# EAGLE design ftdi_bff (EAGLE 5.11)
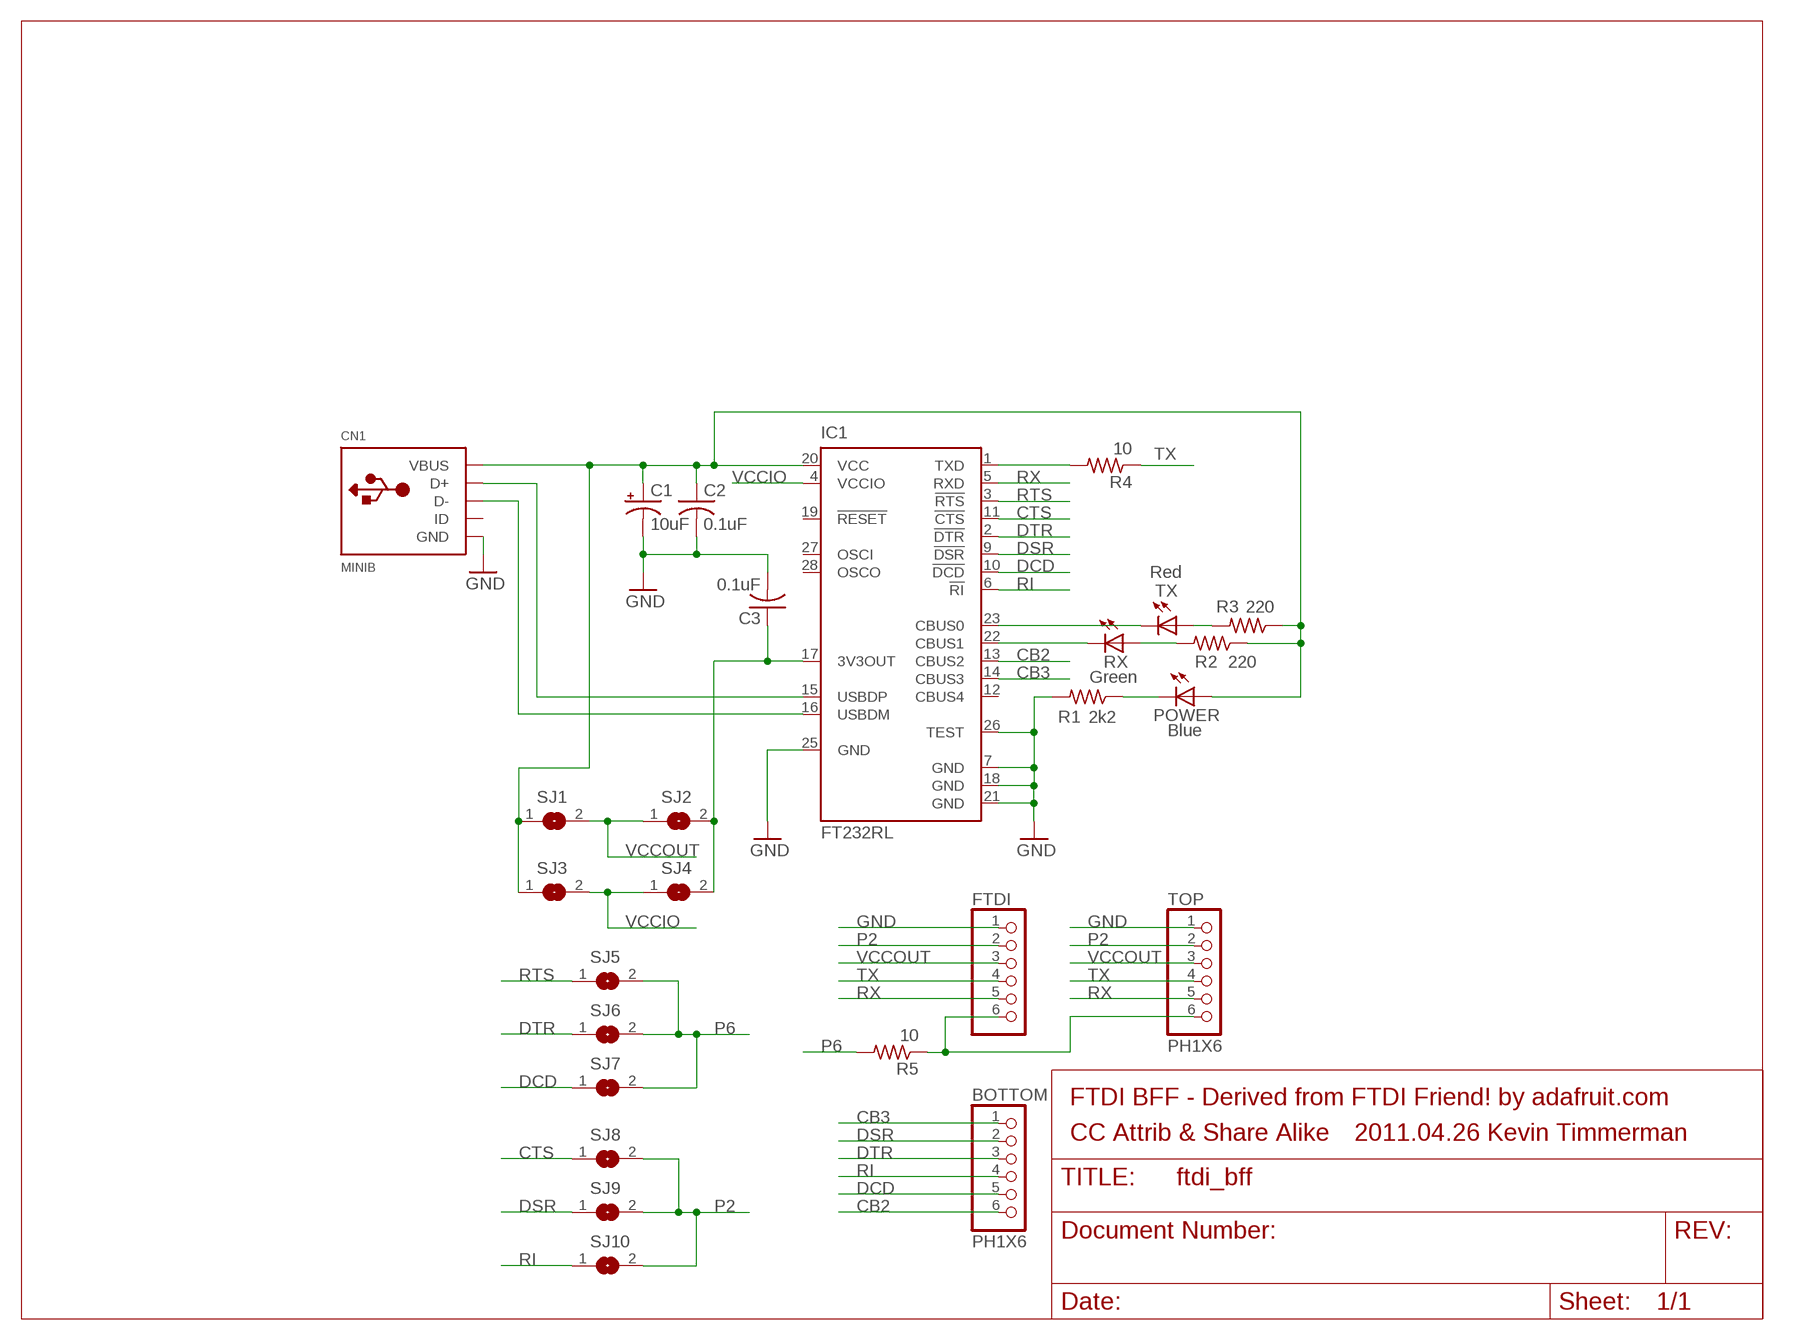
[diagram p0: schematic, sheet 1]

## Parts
BOTTOM  PH1X6  [PH1X6EDGE]
C1  10uF  CPOL-USA/3216-18R  [A/3216-18R]
C2  0.1uF  C-USC0805K  [C0805K]
C3  0.1uF  C-USC0805K  [C0805K]
CN1  MINIB  USBMINIB  [USB-MINIB]
FTDI  PINHD-1X6CB  [1X06-CLEANBIG]
IC1  FT232RL  [SSOP28]
POWER  Blue  LEDCHIP-LED0805  [CHIP-LED0805]
R1  2k2  R-US_R0805  [R0805]
R2  220  R-US_R0805  [R0805]
R3  220  R-US_R0805  [R0805]
R4  10  R-US_R0805  [R0805]
R5  10  R-US_R0805  [R0805]
RX  Green  LEDCHIP-LED0805  [CHIP-LED0805]
SJ1  SJ  [SJ]
SJ2  SJ  [SJ]
SJ3  SJ  [SJ]
SJ4  SJ  [SJ]
SJ5  SJ  [SJ]
SJ6  SJ  [SJ]
SJ7  SJ  [SJ]
SJ8  SJ  [SJ]
SJ9  SJ  [SJ]
SJ10  SJ  [SJ]
TOP  PH1X6  [PH1X6EDGE]
TX  Red  LEDCHIP-LED0805  [CHIP-LED0805]

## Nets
CB2: BOTTOM.6 IC1.13(CBUS2)
CB3: BOTTOM.1 IC1.14(CBUS3)
CTS: IC1.11(!CTS) SJ8.1
DCD: BOTTOM.5 IC1.10(!DCD) SJ7.1
DSR: BOTTOM.2 IC1.9(!DSR) SJ9.1
DTR: BOTTOM.3 IC1.2(!DTR) SJ6.1
GND: C1.- C2.2 C3.2 CN1.GND FTDI.1 IC1.7(GND) IC1.18(GND) IC1.21(GND) IC1.25(GND) IC1.26(TEST) R1.2 TOP.1
N$2: FTDI.6 R5.1 TOP.6
N$3: CN1.D+ IC1.15(USBDP)
N$4: CN1.D- IC1.16(USBDM)
N$5: IC1.1(TXD) R4.2
N$6: IC1.23(CBUS0) TX.C
N$7: IC1.22(CBUS1) RX.C
N$8: R2.2 RX.A
N$9: R3.2 TX.A
N$10: C3.1 IC1.17(3V3OUT) SJ2.2 SJ4.2
N$11: C1.+ C2.1 CN1.VBUS IC1.20(VCC) POWER.A R2.1 R3.1 SJ1.1 SJ3.1
N$13: POWER.C R1.1
P2: FTDI.2 SJ8.2 SJ9.2 SJ10.2 TOP.2
P6: R5.2 SJ5.2 SJ6.2 SJ7.2
RI: BOTTOM.4 IC1.6(!RI) SJ10.1
RTS: IC1.3(!RTS) SJ5.1
RX: FTDI.5 IC1.5(RXD) TOP.5
TX: FTDI.4 R4.1 TOP.4
VCCIO: IC1.4(VCCIO) SJ3.2 SJ4.1
VCCOUT: FTDI.3 SJ1.2 SJ2.1 TOP.3
Unconnected: CN1.ID IC1.12(CBUS4) IC1.19(!RESET) IC1.27(OSCI) IC1.28(OSCO)

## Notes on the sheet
- FTDI BFF - Derived from FTDI Friend! by adafruit.com
- CC Attrib & Share Alike | 2011.04.26 Kevin Timmerman

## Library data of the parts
BOTTOM TOP = MY_CONN:PH1X6
C1 = adafruit:CPOL-US: POLARIZED CAPACITOR, American symbol
C2 C3 = adafruit:C-US: CAPACITOR, American symbol
CN1 = adafruit:USB: USB Connectors USBMINIB - Surface Mount Female Mini-B USB Connector 4UConnector: 06564 By microbuilder.eu Thru-hole RA Female Mini-B USB Connector 4UConnector: 18732 By ladyada.net
FTDI = adafruit:PINHD-1X6: PIN HEADER
IC1 = ftdichip:FT232R: Source: http://www.ftdichip.com/Documents/DataSheets/DS_FT232R_v104.pdf
POWER RX TX = adafruit:LED: LED
R1-R5 = adafruit:R-US_: RESISTOR, American symbol
SJ1-SJ10 = jumper:SJ: SMD solder JUMPER

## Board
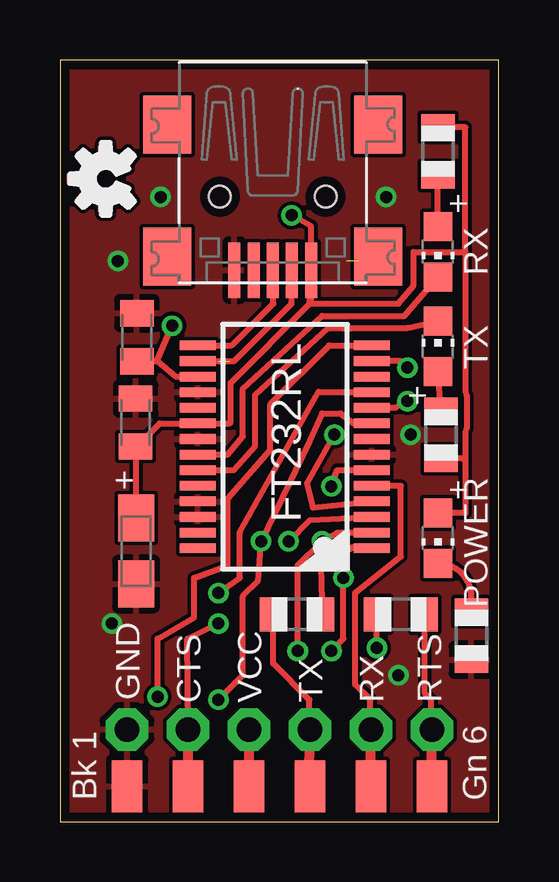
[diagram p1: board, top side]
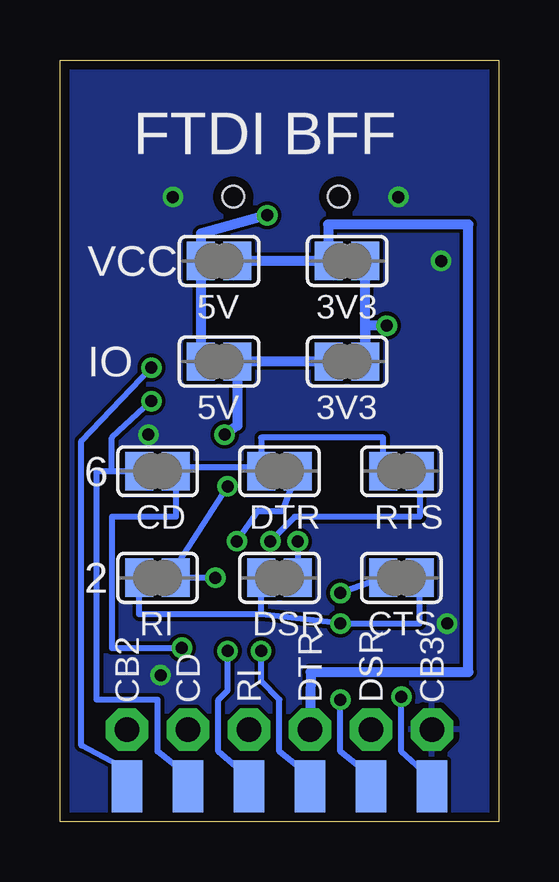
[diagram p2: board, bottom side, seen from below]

Size 18.29 x 31.75 mm. Coordinates in mm from the lower left corner, seen from the top.
Outline: 0,31.75 0,0 18.29,0 18.29,31.75 0,31.75
Copper layers (1*16): Top 0.0356mm / dielectric 1.5011mm / Bottom 0.0356mm
Design rules "LaenPCBOrder": minimum track width 6mil, minimum drill 13mil, track to track 6mil, track to pad 6mil, pad to pad 6mil, via to via 6mil, smd to smd 6mil, copper to edge 15mil, drill to drill 6mil, minimum pad ring 7mil, minimum via ring 7mil, stop-mask expansion 4mil, vias tented up to drill 0mil, thermal gap 10mil

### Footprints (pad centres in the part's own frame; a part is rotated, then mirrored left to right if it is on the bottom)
PH1X6EDGE = smd 2.159 x 1.27: 1 0,0; 2 0,-2.54; 3 0,-5.08; 4 0,-7.62; 5 0,-10.16; 6 0,-12.7
A/3216-18R = smd 1.95 x 1.5: + 1.375,0; - -1.375,0
C0805K = smd 1.1 x 1.4: 1 -1,0; 2 1,0
USB-MINIB = smd 0.5 x 2.308: D+ 0,4.064; D- -0.8,4.064; GND 1.6,4.064; ID 0.8,4.064; VBUS -1.6,4.064 | smd 2 x 2.4: GND1 -4.4,-2; GND2 -4.4,3.5; GND3 4.4,3.5; GND4 4.4,-2 | hole 0.9: -2.2,1; 2.2,1
1X06-CLEANBIG = drill 1.016 pad 1.778 octagon: 1 -6.35,0; 2 -3.81,0; 3 -1.27,0; 4 1.27,0; 5 3.81,0; 6 6.35,0
SSOP28 = smd 0.4 x 1.5: 1 -4.225,-3.625; 2 -3.575,-3.625; 3 -2.925,-3.625; 4 -2.275,-3.625; 5 -1.625,-3.625; 6 -0.975,-3.625; 7 -0.325,-3.625; 8 0.325,-3.625; 9 0.975,-3.625; 10 1.625,-3.625; 11 2.275,-3.625; 12 2.925,-3.625; 13 3.575,-3.625; 14 4.225,-3.625; 15 4.225,3.625; 16 3.575,3.625; 17 2.925,3.625; 18 2.275,3.625; 19 1.625,3.625; 20 0.975,3.625; 21 0.325,3.625; 22 -0.325,3.625; 23 -0.975,3.625; 24 -1.625,3.625; 25 -2.275,3.625; 26 -2.925,3.625; 27 -3.575,3.625; 28 -4.225,3.625
CHIP-LED0805 = smd 1.2 x 1.2: A 0,-1.05; C 0,1.05
R0805 = smd 1.1 x 1.4: 1 -1,0; 2 1,0
SJ = smd 1.168 x 1.6: 1 -0.762,0; 2 0.762,0

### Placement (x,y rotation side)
BOTTOM  2.79,1.47 270 bottom
C1  3.17,11.28 90 top
C2  3.15,16.64 90 top
C3  3.2,20.19 90 top
CN1  8.86,27.05 180 top
FTDI  9.14,3.84 0 top
IC1  9.37,15.62 90 top
POWER  15.75,11.81 180 top
R1  17.14,7.75 270 top
R2  15.75,27.94 270 top
R3  15.88,16.13 90 top
R4  9.88,8.64 0 top
R5  14.2,8.64 180 top
RX  15.75,23.75 180 top
SJ1  11.66,23.37 0 bottom
SJ2  6.32,23.37 0 bottom
SJ3  11.66,19.18 0 bottom
SJ4  6.32,19.18 0 bottom
SJ5  4.06,14.61 180 bottom
SJ6  9.14,14.61 180 bottom
SJ7  14.22,14.61 0 bottom
SJ8  4.06,10.16 0 bottom
SJ9  9.14,10.16 180 bottom
SJ10  14.22,10.16 180 bottom
TOP  2.79,1.47 90 top
TX  15.75,19.81 0 top

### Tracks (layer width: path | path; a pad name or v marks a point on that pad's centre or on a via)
CB2  (via drill 0.5)
  Top 0.254: v14.48,18.92 14.21,19.2 IC1.13
  Bottom 0.254: BOTTOM.6 15.49,2.16 17.4,3.17 17.4,15.88 v14.48,18.92
CB3  (via drill 0.5)
  Top 0.254: IC1.14 11.21,19.85 8.76,17.4 8.76,15.49 6.99,13.46 6.99,10.67 5.59,10.16 5.59,8.51 4.06,7.62 v4.06,5.21
  Bottom 0.254: v4.06,5.21 4.06,2.92 2.79,1.78 BOTTOM.1
CTS  (via drill 0.5)
  Top 0.254: IC1.11 12.43,17.9 12.42,17.91 10.77,17.91 7.49,12.06 7.49,10.16 v6.6,9.53
  Bottom 0.254: SJ8.1 v6.6,9.53
DCD  (via drill 0.5)
  Top 0.254: IC1.10 13.97,17.25 v14.48,17.53
  Bottom 0.254: 16.13,14.61 16.76,14.61 16.76,5.08 14.22,5.08 14.22,2.92 12.95,1.91 BOTTOM.5 | 16.13,14.61 SJ7.1 | 16.13,14.61 16.13,16 v14.48,17.53
DSR  (via drill 0.5)
  Top 0.254: IC1.9 12.23,16.6 11.68,17.02 10.92,17.02 10.41,15.88 v8.38,11.68 8.26,10.03 7.62,9.4 7.62,6.1 v6.6,5.08
  Bottom 0.254: v8.38,11.68 SJ9.1 | BOTTOM.2 5.33,1.91 6.6,2.92 v6.6,5.08
DTR  (via drill 0.5)
  Top 0.254: IC1.2 11.56,12.05 v10.92,11.68 9.91,10.67 v9.91,7.11
  Bottom 0.254: v10.92,11.68 10.03,12.95 9.02,12.95 SJ6.1 | BOTTOM.3 7.87,1.91 9.14,2.92 9.14,5.08 9.91,5.84 v9.91,7.11
GND  (via drill 0.5)
  other vias: 14.1,6.1 2.41,23.37 2.16,8.26 14.61,16.13 13.59,26.04 4.19,26.04
  pour Top: 18.29,31.75 0,31.75 0,0 18.29,0
  pour Bottom: 0,0 18.29,0 18.29,31.75 0,31.75
N$1
  Bottom 0.254: 3.81,10.16 4.32,10.16
N$2
  Top 0.254: R5.1 15.2,5.35 15.47,5.08 FTDI.6
  Top 0.406: 15.47,1.47 TOP.6 FTDI.6
N$3
  Top 0.254: CN1.D+ 8.89,21.59 7.15,19.85 IC1.15
N$4
  Top 0.254: CN1.D- 9.65,22.97 9.65,21.59 7.26,19.2 IC1.16
N$5
  Top 0.254: R4.2 10.79,8.64 10.94,8.49 10.88,10.65 12.19,11.43 IC1.1
N$6
  Top 0.254: 5.31,14.61 5.27,14.65 IC1.23 7.24,14.65 8.13,15.66 8.13,17.78 11.18,20.57 14.48,20.57 TX.C
N$7
  Top 0.254: RX.C 14.35,21.08 10.92,21.08 7.62,18.03 7.62,16.06 6.99,15.3 IC1.22
N$8
  Top 0.254: RX.A R2.2
N$9
  Top 0.254: R3.2 TX.A
N$10  (via drill 0.5)
  Top 0.254: C3.1 4.05,19.19 | 4.05,19.19 4.83,18.54 IC1.17 | 4.05,19.19 4.04,19.18 v4.67,20.68
  Bottom 0.406: SJ2.2 SJ4.2 5.56,20.68 v4.67,20.68
N$11  (via drill 0.5)  (1 unrouted)
  Top 0.254: C1.+ 3.17,15.75 3.15,15.72 C2.1 3.19,15.64 4.15,16.6 IC1.20 7.07,16.6 7.11,16.64 7.11,18.29 10.41,21.59 | CN1.VBUS 10.41,22.94 10.41,21.59 | R2.1 16.89,28.94 16.89,23.75 | 16.89,23.75 16.89,17.91 16.94,17.78 16.94,16.38 16.89,16.26 16.89,15.24 | CN1.VBUS 10.46,21.64 10.41,21.59 | 10.41,21.59 14.1,21.59 14.73,22.35 14.73,23.75 16.89,23.75 | CN1.VBUS 10.46,24.82 v9.65,25.27 | R3.1 16.78,15.13 arc90 16.89,15.24 | 16.89,15.24 16.89,12.86 POWER.A
  Bottom 0.254: 11.43,23.37 11.94,23.37
  Bottom 0.406: v9.65,25.27 12.42,24.51 SJ1.1 SJ3.1
N$12
  Bottom 0.254: 3.81,14.61 4.32,14.61
N$13
  Top 0.254: POWER.C arc-90 17.14,9.36 R1.1
N$14
  Top 0.203: 2.87,27.2 arc9 2.79,27.35 3.11,27.73 2.84,28 2.46,27.69 arc19 2.14,27.82 2.09,28.31 1.72,28.31 1.67,27.82 arc19 1.35,27.69 0.97,28 0.7,27.73 1.02,27.35 arc19 0.88,27.03 0.39,26.98 0.39,26.61 0.88,26.56 arc19 1.02,26.24 0.7,25.86 0.97,25.6 1.35,25.91 arc19 1.67,25.78 1.72,25.28 2.09,25.28 2.14,25.78 arc19 2.46,25.91 2.84,25.6 3.11,25.86 2.79,26.24 arc9 2.87,26.4 2.35,26.61 arc-67 1.91,26.32 arc-247 2.35,26.98 2.87,27.2
P2  (via drill 0.5)
  Top 0.254: FTDI.2 5.31,7.62 v6.6,8.26
  Top 0.406: 5.31,1.47 TOP.2 FTDI.2
  Bottom 0.254: SJ8.2 3.3,8.26 v6.6,8.26 9.91,8.64 | 9.91,8.64 14.99,8.64 SJ10.2 | 9.91,8.64 SJ9.2
P6  (via drill 0.5)
  Top 0.254: v13.21,7.24 R5.2
  Bottom 0.254: SJ5.2 4.83,16 9.91,16 9.91,14.76 | v13.21,7.24 16.13,7.24 16.13,12.7 13.46,12.7 SJ7.2 12.95,14.76 9.91,14.76 | 9.91,14.76 SJ6.2
RI  (via drill 0.5)
  Top 0.254: IC1.6 11.56,14.65 v11.3,13.97 | v11.3,7.11 11.81,7.62 v11.81,10.16
  Bottom 0.254: v11.3,13.97 13.34,10.79 SJ10.1 v11.81,10.16 | BOTTOM.4 10.41,2.16 10.79,2.16 11.68,2.92 11.68,5.08 11.3,5.46 v11.3,7.11
RTS  (via drill 0.5)
  Top 0.254: IC1.3 10.41,12.57 v9.53,11.68
  Bottom 0.254: v9.53,11.68 8.51,12.7 3.3,12.7 SJ5.1
RX
  Top 0.254: IC1.5 14.2,14 14.2,11.05 12.29,9.53 12.29,5.71 12.93,5.11 FTDI.5
  Top 0.406: 12.93,1.47 TOP.5 FTDI.5
TX
  Top 0.254: R4.1 8.88,6.59 10.39,5.08 FTDI.4
  Top 0.406: TOP.4 10.39,1.47 FTDI.4
VCCIO  (via drill 0.5)  (1 unrouted)
  Top 0.254: IC1.4 10.54,13.09 10.29,14.1 v11.43,16.13
  Bottom 0.254: 6.1,19.18 6.6,19.18
  Bottom 0.406: SJ4.1 SJ3.2 10.9,16.51 v11.43,16.13
VCCOUT
  Top 0.406: 7.85,1.47 TOP.3 FTDI.3
  Bottom 0.254: 7.34,23.62 SJ2.1 7.09,23.24 7.11,23.24
  Bottom 0.406: 7.11,23.24 7.11,24.89 1.27,24.89 1.27,6.22 7.85,6.22 FTDI.3 | SJ2.1 SJ1.2

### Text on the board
tPlace: GND | CTS | VCC | TX | RX | RTS | Bk 1 | Gn 6
bPlace: FTDI BFF | VCC | 3V3 | 5V | IO | 3V3 | 5V | 6 | RTS | DTR | CD | 2 | CTS | DSR | RI | CB3 | DSR | DTR | RI | CD | CB2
